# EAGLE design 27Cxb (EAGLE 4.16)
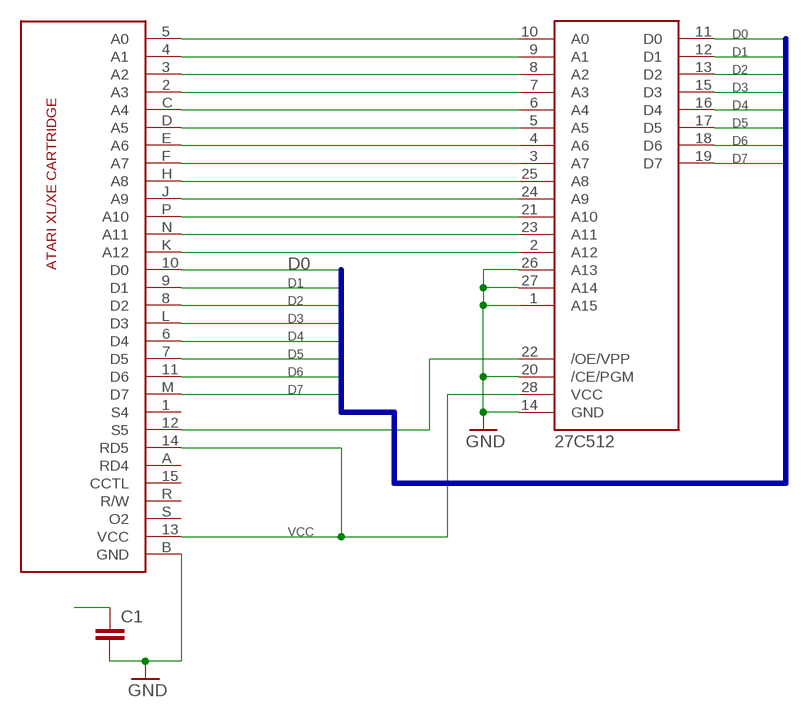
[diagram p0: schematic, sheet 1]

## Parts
C1  C5/5.5  [C5B5.5]
IC2  27C512  [DIL28-6]
U$1  CARTRIDGE  [IBM8BIT]

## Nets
A0: IC2.10(A0) U$1.5(A0)
A1: IC2.9(A1) U$1.4(A1)
A2: IC2.8(A2) U$1.3(A2)
A3: IC2.7(A3) U$1.2(A3)
A4: IC2.6(A4) U$1.C(A4)
A5: IC2.5(A5) U$1.D(A5)
A6: IC2.4(A6) U$1.E(A6)
A7: IC2.3(A7) U$1.F(A7)
A8: IC2.25(A8) U$1.H(A8)
A9: IC2.24(A9) U$1.J(A9)
A10: IC2.21(A10) U$1.P(A10)
A11: IC2.23(A11) U$1.N(A11)
A12: IC2.2(A12) U$1.K(A12)
D0: IC2.11(D0) U$1.10(D0)
D1: IC2.12(D1) U$1.9(D1)
D2: IC2.13(D2) U$1.8(D2)
D3: IC2.15(D3) U$1.L(D3)
D4: IC2.16(D4) U$1.6(D4)
D5: IC2.17(D5) U$1.7(D5)
D6: IC2.18(D6) U$1.11(D6)
D7: IC2.19(D7) U$1.M(D7)
GND: C1.2 IC2.1(A15) IC2.14(GND) IC2.20(/CE/PGM) IC2.26(A13) IC2.27(A14) U$1.B(GND)
S5: IC2.22(/OE/VPP) U$1.12(S5)
VCC: C1.1 IC2.28(VCC) U$1.13(VCC) U$1.14(RD5)
Unconnected: U$1.1(S4) U$1.15(CCTL) U$1.A(RD4) U$1.R(R/W) U$1.S(O2)

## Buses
D

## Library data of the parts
C1 = capacitor-wima:C: CAPACITOR
IC2 = LevoROMS:27C512*: 27C512 High Performance CMOS EPROM
U$1 = ataricart:CARTRIDGE: 8 bit Atari cartridge Versija 1.0. Rodos gera.

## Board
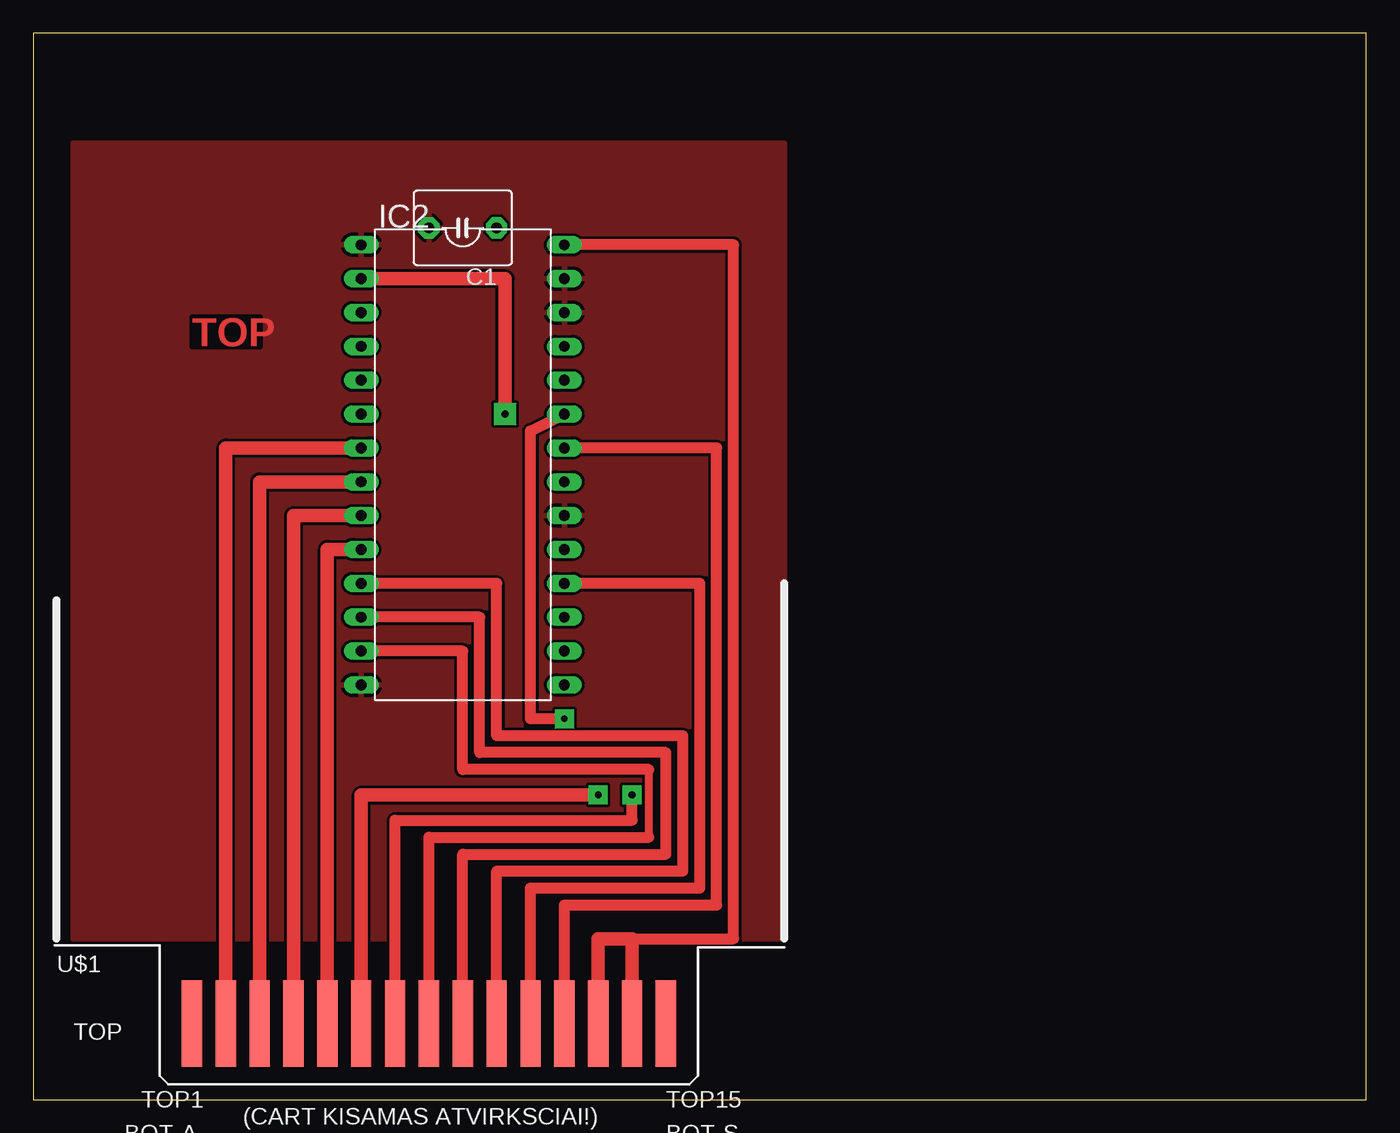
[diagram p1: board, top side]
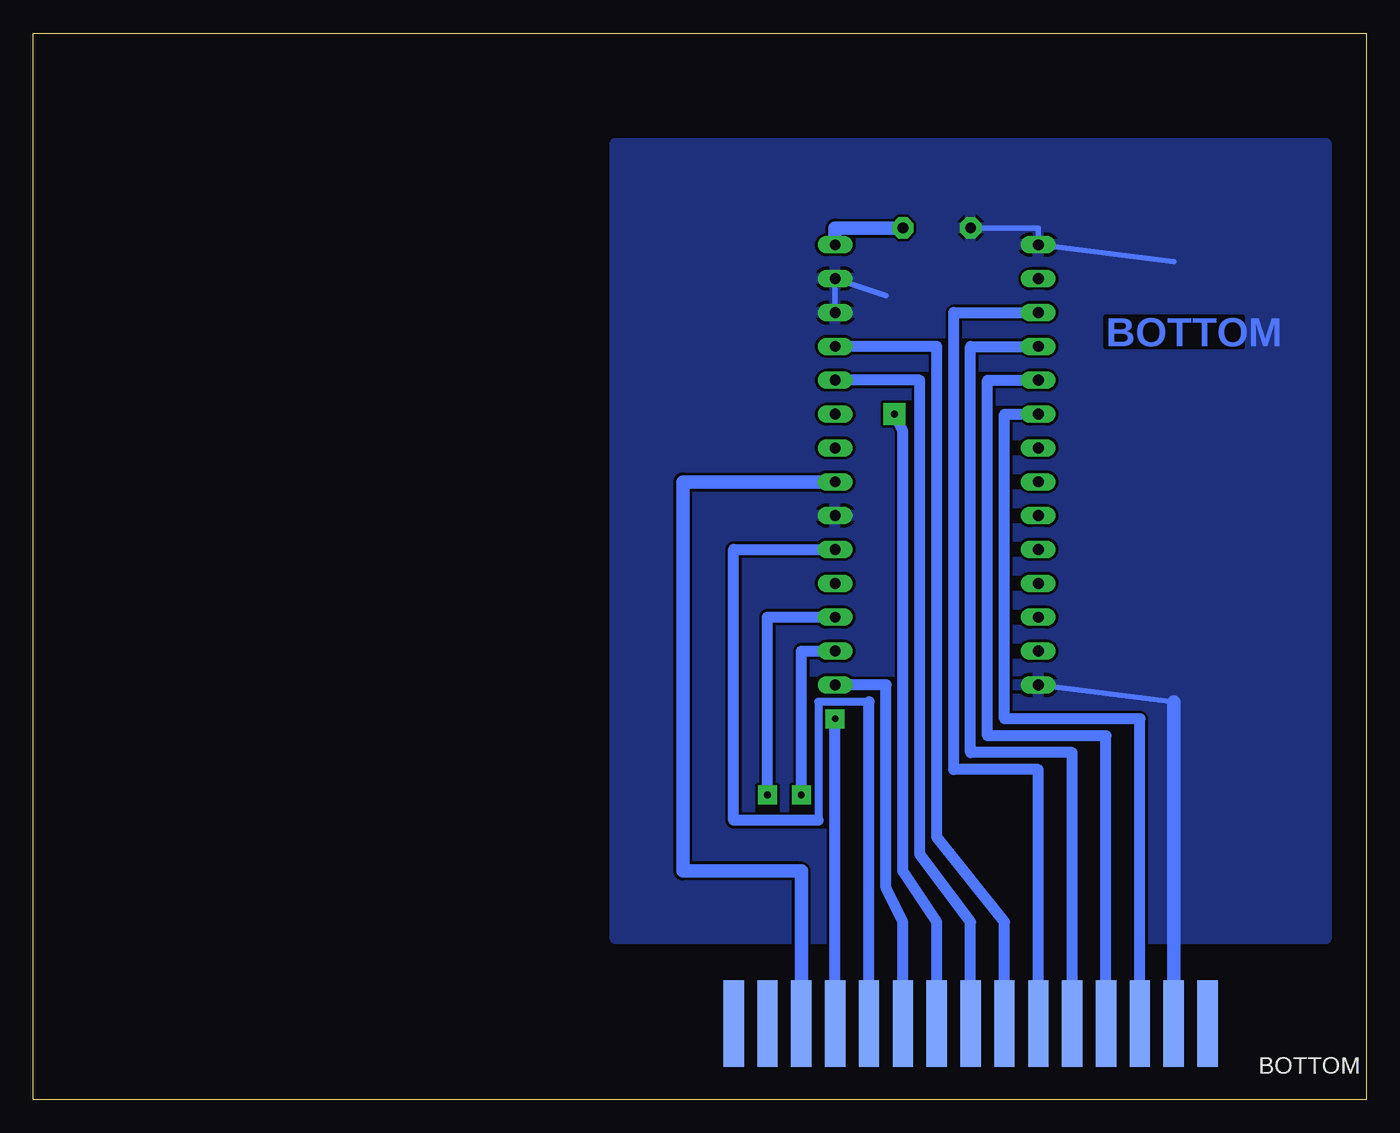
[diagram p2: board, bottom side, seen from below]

Size 100 x 80 mm. Coordinates in mm from the lower left corner, seen from the top.
Outline: 0,0 100,0 100,80 0,80 0,0
Copper layers (1*16): Top 0.035mm / dielectric 1.5mm / Bottom 0.035mm
Design rules "default": minimum track width 10mil, minimum drill 24mil, track to track 8mil, track to pad 8mil, pad to pad 8mil, via to via 8mil, smd to smd 8mil, copper to edge 40mil, drill to drill 8mil, minimum pad ring 10mil, minimum via ring 8mil, stop-mask expansion 4mil, vias tented up to drill 0mil, thermal gap 10mil

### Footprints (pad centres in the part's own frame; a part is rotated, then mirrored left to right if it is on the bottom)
C5B5.5 = drill 0.813 pad 1.6 octagon: 1 -2.54,0; 2 2.54,0
DIL28-6 = drill 0.813 long: 1 -16.51,-7.62; 2 -13.97,-7.62; 3 -11.43,-7.62; 4 -8.89,-7.62; 5 -6.35,-7.62; 6 -3.81,-7.62; 7 -1.27,-7.62; 8 1.27,-7.62; 9 3.81,-7.62; 10 6.35,-7.62; 11 8.89,-7.62; 12 11.43,-7.62; 13 13.97,-7.62; 14 16.51,-7.62; 15 16.51,7.62; 16 13.97,7.62; 17 11.43,7.62; 18 8.89,7.62; 19 6.35,7.62; 20 3.81,7.62; 21 1.27,7.62; 22 -1.27,7.62; 23 -3.81,7.62; 24 -6.35,7.62; 25 -8.89,7.62; 26 -11.43,7.62; 27 -13.97,7.62; 28 -16.51,7.62
IBM8BIT = smd 1.524 x 6.477: 1 -16.51,-5.08; 2 -13.97,-5.08; 3 -11.43,-5.08; 4 -8.89,-5.08; 5 -6.35,-5.08; 6 -3.81,-5.08; 7 -1.27,-5.08; 8 1.27,-5.08; 9 3.81,-5.08; 10 6.35,-5.08; 11 8.89,-5.08; 12 11.43,-5.08; 13 13.97,-5.08; 14 16.51,-5.08; 15 19.05,-5.08 | smd 1.524 x 6.477 bottom: A -16.51,-5.08; B -13.97,-5.08; C -11.43,-5.08; D -8.89,-5.08; E -6.35,-5.08; F -3.81,-5.08; H -1.27,-5.08; J 1.27,-5.08; K 3.81,-5.08; L 6.35,-5.08; M 8.89,-5.08; N 11.43,-5.08; P 13.97,-5.08; R 16.51,-5.08; S 19.05,-5.08

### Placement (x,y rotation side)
C1  32.22,65.4 180 top
IC2  32.22,47.62 270 top
U$1  28.41,10.79 0 top

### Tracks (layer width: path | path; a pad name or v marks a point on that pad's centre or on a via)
A0
  Top 1.016: IC2.10 22.06,41.27 U$1.5
A1
  Top 1.016: IC2.9 19.52,43.81 U$1.4
A2
  Top 1.016: U$1.3 16.98,46.35 IC2.8
A3
  Top 1.016: U$1.2 14.44,48.89 IC2.7
A4
  Bottom 0.813: U$1.C 16.98,28.57 27.14,28.57 27.14,51.43 IC2.6
A5
  Bottom 0.813: U$1.D 19.52,27.3 28.41,27.3 28.41,53.97 IC2.5
A6
  Bottom 0.813: U$1.E 22.06,26.03 29.68,26.03 29.68,56.51 IC2.4
A7
  Bottom 0.813: U$1.F 24.6,24.76 30.95,24.76 30.95,59.05 IC2.3
A8
  Bottom 0.813: U$1.H 27.14,13.33 32.22,19.68 32.22,56.51 IC2.25
A9
  Bottom 0.813: U$1.J 29.68,13.33 33.49,18.41 33.49,53.97 IC2.24
A10
  Bottom 1.016: U$1.P 42.38,17.14 51.27,17.14 51.27,46.35 IC2.21
A11  (via drill 0.5 pad 1.42)
  Top 0.813: IC2.23 37.3,50.16 37.3,28.57 v39.84,28.57
  Bottom 0.813: U$1.N v39.84,28.57
A12  (via drill 0.5 pad 1.68)
  Top 1.016: v35.39,51.43 35.39,61.59 IC2.2
  Bottom 0.813: U$1.K 32.22,13.33 34.76,17.14 34.76,50.16 v35.39,51.43
D0
  Top 0.813: IC2.11 34.76,38.73 34.76,27.3 48.73,27.3 48.73,17.14 34.76,17.14 U$1.10
D1
  Top 0.813: U$1.9 32.22,18.41 47.46,18.41 47.46,26.03 33.49,26.03 33.49,36.19 IC2.12
D2
  Top 0.61: 46.19,19.68 46.19,24.76
  Top 0.813: U$1.8 29.68,19.68 46.19,19.68 | 46.19,24.76 32.22,24.76 32.22,33.65 IC2.13
D3
  Bottom 0.813: U$1.L 34.76,13.33 36.03,15.87 36.03,31.11 IC2.15
D4  (via drill 0.5 pad 1.42)
  Top 1.016: U$1.6 24.6,22.86 v42.38,22.86
  Bottom 0.813: v42.38,22.86 42.38,33.65 IC2.16
D5  (via drill 0.5 pad 1.42)
  Top 0.813: U$1.7 27.14,20.95 44.92,20.95 v44.92,22.86
  Bottom 0.813: v44.92,22.86 44.92,36.19 IC2.17
D6
  Top 0.813: U$1.11 37.3,15.87 50,15.87 50,38.73 IC2.18
D7
  Bottom 0.61: 37.3,29.84 41.11,29.84 41.11,20.95
  Bottom 0.813: U$1.M 37.3,29.84 | 41.11,20.95 47.46,20.95 47.46,41.27 IC2.19
GND
  Bottom 0.406: C1.2 24.6,65.4 IC2.1 14.44,62.86 | 36.03,60.32 IC2.27 IC2.26 | 14.44,29.84 IC2.14
  Bottom 1.016: U$1.B 14.44,29.84
  pour Bottom: 3.01,71.75 3.01,12.06 56.35,12.06 56.35,71.75
  pour Top: 3.01,71.75 3.01,12.06 56.35,12.06 56.35,71.75
S5
  Top 0.813: U$1.12 39.84,14.6 51.27,14.6 51.27,48.89 IC2.22
VCC
  Top 0.813: 44.92,12.06 52.54,12.06 52.54,64.13 IC2.28
  Top 1.016: U$1.13 42.38,12.06 44.92,12.06 U$1.14
  Bottom 1.016: C1.1 39.84,65.4 IC2.28

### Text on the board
Top: TOP
Bottom: BOTTOM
